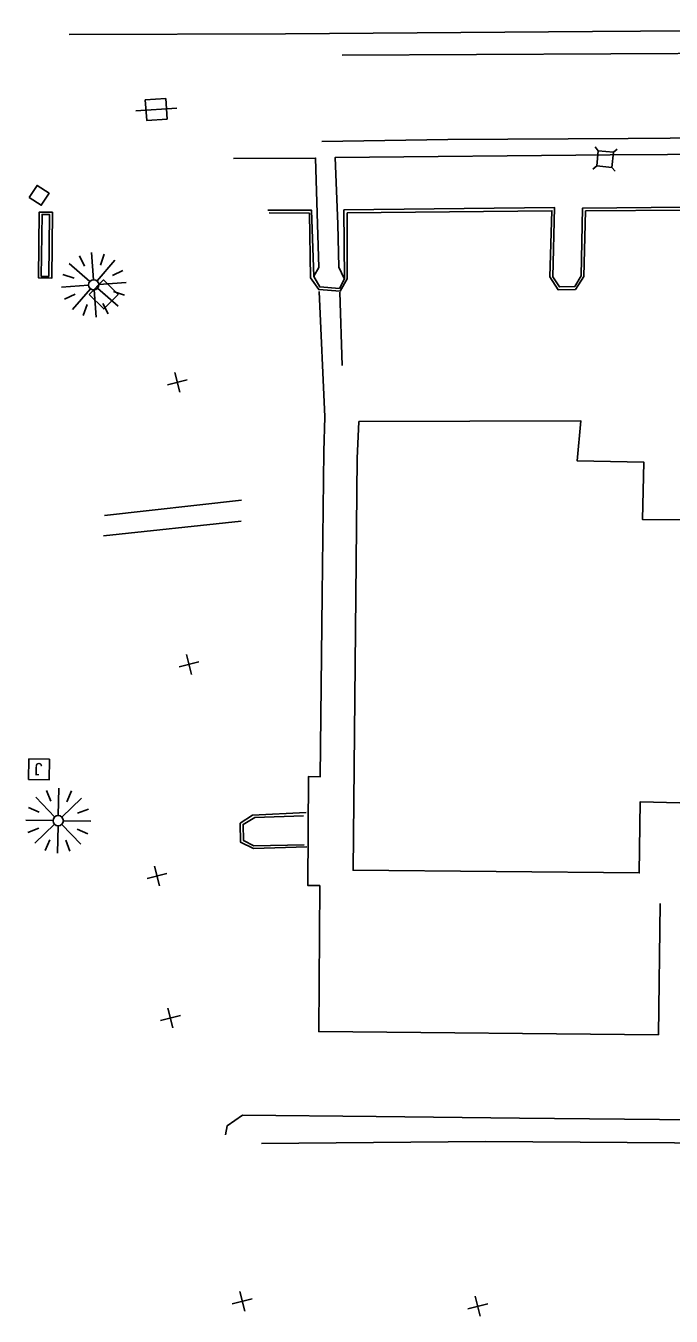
# Model space of a CAD drawing. Extents: x 4711259 to 4716401, y 890074 to 892728.
# Drawn here: x 4711259.2 to 4711416.6, y 891002.7 to 891317.2 of the extents above; entities that cross this region are included whole.
import ezdxf

# ---------------------------------------------------------------- set-up
doc = ezdxf.new("R2010")
doc.units = 0
for name, color, linetype in [('E_HY_STORM_Inlet', 7, 'Continuous'), ('E_RDWY_PHOTOG_Eave', 7, 'Continuous'), ('E_RDWY_ROAD_Curb', 7, 'Continuous'), ('E_RDWY_ROAD_EdgeConc', 7, 'Continuous'), ('E_RDWY_ROAD_Sidewalk', 7, 'Continuous'), ('E_RDWY_ROAD_Striping', 7, 'Continuous'), ('E_RDWY_ROAD_TBofCurb', 7, 'Continuous'), ('E_TERR_DTM_BrkLines', 7, 'Continuous'), ('E_TERR_DTM_RandomPt', 7, 'Continuous'), ('E_TRAF_ILLUM_Poles', 7, 'Continuous'), ('E_TRAF_PHOTOG_Signs', 7, 'Continuous'), ('E_UTIL_COMM_General', 7, 'Continuous'), ('E_UTIL_ELEC_GENERAL', 7, 'Continuous'), ('E_UTIL_ELEC_POLE', 7, 'Continuous'), ('E_UTIL_WTR_General', 7, 'Continuous')]:
    doc.layers.add(name, color=color, linetype=linetype)

msp = doc.modelspace()

# ---------------------------------------------------------------- linework, layer by layer
at = {"layer": 'E_HY_STORM_Inlet'}
msp.add_line((4711278.2, 891251.75), (4711278.2, 891251.75), dxfattribs=at)
msp.add_lwpolyline([(4711274.66, 891251.72), (4711278.17, 891255.28), (4711281.73, 891251.77), (4711278.22, 891248.21)], close=True, dxfattribs=at)
at = {"layer": 'E_RDWY_PHOTOG_Eave'}
msp.add_lwpolyline([(4711532.58, 891196.13), (4711493.22, 891196.36), (4711493.39, 891196.48), (4711409.65, 891196.87), (4711409.96, 891210.86), (4711393.66, 891211.19), (4711394.58, 891220.96), (4711340.47, 891220.75), (4711340.05, 891211.74), (4711339.04, 891111.37), (4711408.85, 891110.73), (4711409.1, 891128.06), (4711492.84, 891125.95), (4711531.9, 891125.61), (4711532.65, 891196.06)], dxfattribs=at)
at = {"layer": 'E_RDWY_ROAD_Curb'}
for points in [[(4711336.39, 891310.08), (4711434.66, 891310.58), (4711510.87, 891310.89), (4711572.62, 891311.17), (4711615.1, 891311.7)], [(4711318.59, 891271.61), (4711328.4, 891271.56), (4711328.68, 891255.8), (4711330.67, 891252.93), (4711335.93, 891252.55), (4711337.64, 891255.54), (4711337.63, 891271.62), (4711387.56, 891272.15), (4711387, 891256.05), (4711389.04, 891252.91), (4711393.27, 891252.99), (4711395.34, 891256.11), (4711395.75, 891272.12), (4711444.67, 891272.45)], [(4711327.63, 891125.43), (4711314.5, 891124.81), (4711311.5, 891122.83), (4711311.6, 891118.21), (4711314.74, 891116.66), (4711327.76, 891117.05)]]:
    msp.add_lwpolyline(points, dxfattribs=at)
at = {"layer": 'E_RDWY_ROAD_EdgeConc'}
msp.add_lwpolyline([(4711265.75, 891271.8), (4711265.58, 891255.74), (4711262.34, 891255.77), (4711262.51, 891271.83)], close=True, dxfattribs=at)
for points in [[(4711413.91, 891103.29), (4711413.52, 891071.28), (4711330.67, 891072.04), (4711330.92, 891107.64), (4711327.97, 891107.7), (4711328.2, 891134.27), (4711331.05, 891134.18), (4711331.53, 891178.5), (4711331.91, 891213.47), (4711332.13, 891221.94), (4711330.76, 891252.45)], [(4711335.81, 891252.3), (4711336.38, 891234.39)], [(4711311.8, 891201.62), (4711278.43, 891197.88)], [(4711278.15, 891192.9), (4711311.77, 891196.5)]]:
    msp.add_lwpolyline(points, dxfattribs=at)
at = {"layer": 'E_RDWY_ROAD_Sidewalk'}
for points in [[(4711620.01, 891291.07), (4711550.39, 891290.38), (4711491.78, 891290.18), (4711436.87, 891289.98), (4711406.11, 891289.74), (4711362.14, 891289.55)], [(4711331.46, 891289.05), (4711362.14, 891289.55)], [(4711329.48, 891256.17), (4711330.65, 891258.3), (4711330.37, 891268.91), (4711329.88, 891285.01), (4711309.9, 891284.91)], [(4711336.87, 891255.64), (4711335.57, 891258.42), (4711335.29, 891268.88), (4711334.66, 891285.1), (4711401.76, 891285.78), (4711471.79, 891286.18), (4711521.53, 891286.27), (4711576.93, 891286.64), (4711616.2, 891287.07), (4711620.16, 891287.14)]]:
    msp.add_lwpolyline(points, dxfattribs=at)
at = {"layer": 'E_RDWY_ROAD_Striping'}
msp.add_lwpolyline([(4711269.83, 891315.08), (4711322.53, 891315.28), (4711397.46, 891315.84), (4711456.03, 891316.25), (4711477.12, 891316.43), (4711546.25, 891316.78), (4711614.88, 891317.24)], dxfattribs=at)
at = {"layer": 'E_RDWY_ROAD_TBofCurb'}
for points in [[(4711336.8, 891272.38), (4711336.92, 891255.53), (4711335.73, 891253.21), (4711330.93, 891253.58), (4711329.44, 891256.1), (4711328.91, 891272.27), (4711318.29, 891272.31)], [(4711445.3, 891273.26), (4711394.99, 891272.77), (4711394.69, 891256.27), (4711393.13, 891253.71), (4711389.37, 891253.59), (4711387.77, 891256.08), (4711388.19, 891272.94), (4711336.8, 891272.38)], [(4711327.11, 891117.57), (4711314.87, 891117.31), (4711312.34, 891118.6), (4711312.21, 891122.54), (4711315.07, 891124.27), (4711326.93, 891124.62)], [(4711483.13, 891070.27), (4711480.91, 891070.32), (4711478.17, 891069.61), (4711475.63, 891065.85), (4711475.19, 891049.99), (4711430.84, 891050.48), (4711379.63, 891050.94), (4711344.67, 891051.38), (4711312.04, 891051.7), (4711308.36, 891049.09), (4711307.92, 891046.89)]]:
    msp.add_lwpolyline(points, dxfattribs=at)
at = {"layer": 'E_TERR_DTM_BrkLines'}
msp.add_lwpolyline([(4711316.73, 891044.73), (4711371.36, 891045.25), (4711429.02, 891044.86), (4711485.37, 891044.42), (4711545.06, 891043.32), (4711590.92, 891041.62), (4711616.39, 891039.65)], dxfattribs=at)
at = {"layer": 'E_TERR_DTM_RandomPt'}
for p, q in [((4711298.59, 891230.94), (4711293.75, 891229.69)), ((4711295.55, 891232.74), (4711296.8, 891227.9)), ((4711301.45, 891162.18), (4711296.61, 891160.93)), ((4711298.4, 891163.97), (4711299.65, 891159.13)), ((4711290.58, 891112.4), (4711291.83, 891107.56)), ((4711293.62, 891110.61), (4711288.78, 891109.35)), ((4711293.87, 891077.78), (4711295.12, 891072.94)), ((4711296.92, 891075.99), (4711292.08, 891074.74)), ((4711311.42, 891008.71), (4711312.62, 891003.86)), ((4711314.45, 891006.89), (4711309.59, 891005.69)), ((4711371.88, 891005.69), (4711367.03, 891004.49)), ((4711368.86, 891007.52), (4711370.06, 891002.67))]:
    msp.add_line(p, q, dxfattribs=at)
at = {"layer": 'E_TRAF_ILLUM_Poles'}
for p, q in [((4711274.84, 891254.91), (4711269.8, 891259.28)), ((4711273.54, 891258.64), (4711272.28, 891261.19)), ((4711275.69, 891255.34), (4711275.22, 891261.99)), ((4711276.6, 891255.04), (4711280.97, 891260.07)), ((4711277.41, 891258.89), (4711278.33, 891261.59)), ((4711270.99, 891255.72), (4711268.29, 891256.64)), ((4711282.88, 891257.59), (4711280.33, 891256.34)), ((4711274.54, 891254), (4711267.89, 891253.53)), ((4711274.96, 891253.15), (4711270.6, 891248.11)), ((4711276.73, 891253.27), (4711281.76, 891248.91)), ((4711277.03, 891254.18), (4711283.68, 891254.66)), ((4711271.23, 891251.85), (4711268.68, 891250.59)), ((4711275.87, 891252.85), (4711276.35, 891246.2)), ((4711283.28, 891251.55), (4711280.58, 891252.46)), ((4711273.24, 891246.6), (4711274.15, 891249.3)), ((4711279.28, 891246.99), (4711278.02, 891249.54)), ((4711265.31, 891128.18), (4711264.28, 891130.84)), ((4711267.15, 891124.71), (4711267.28, 891131.37)), ((4711270.34, 891130.7), (4711269.19, 891128.09)), ((4711266.26, 891124.36), (4711261.64, 891129.16)), ((4711268.03, 891124.33), (4711272.83, 891128.95)), ((4711262.5, 891125.51), (4711259.89, 891126.66)), ((4711274.52, 891126.31), (4711271.86, 891125.28)), ((4711265.88, 891123.48), (4711259.22, 891123.6)), ((4711262.41, 891121.63), (4711259.75, 891120.61)), ((4711266.23, 891122.59), (4711261.43, 891117.96)), ((4711267.11, 891122.21), (4711266.99, 891115.54)), ((4711268, 891122.56), (4711272.62, 891117.76)), ((4711268.38, 891123.43), (4711275.05, 891123.31)), ((4711274.37, 891120.25), (4711271.77, 891121.4)), ((4711265.08, 891118.82), (4711263.92, 891116.22)), ((4711269.98, 891116.07), (4711268.96, 891118.73))]:
    msp.add_line(p, q, dxfattribs=at)
for centre in [(4711275.78, 891254.09), (4711267.13, 891123.46)]:
    msp.add_circle(centre, 1.25, dxfattribs=at)
at = {"layer": 'E_TRAF_PHOTOG_Signs'}
msp.add_lwpolyline([(4711264.81, 891256.12), (4711264.99, 891271.24), (4711263.17, 891271.26), (4711262.99, 891256.14)], close=True, dxfattribs=at)
at = {"layer": 'E_UTIL_COMM_General'}
msp.add_lwpolyline([(4711260.05, 891275.4), (4711261.98, 891278.32), (4711264.9, 891276.4), (4711262.98, 891273.48)], close=True, dxfattribs=at)
at = {"layer": 'E_UTIL_ELEC_GENERAL'}
msp.add_lwpolyline([(4711259.98, 891138.51), (4711264.98, 891138.42), (4711264.88, 891133.42), (4711259.88, 891133.52)], close=True, dxfattribs=at)
at = {"layer": 'E_UTIL_ELEC_POLE'}
msp.add_line((4711286.04, 891296.52), (4711296.02, 891297.17), dxfattribs=at)
msp.add_lwpolyline([(4711288.37, 891299.18), (4711293.36, 891299.5), (4711293.69, 891294.52), (4711288.7, 891294.19)], close=True, dxfattribs=at)
at = {"layer": 'E_UTIL_WTR_General'}
for p, q in [((4711398.85, 891286.8), (4711398.11, 891287.72)), ((4711402.58, 891286.42), (4711403.49, 891287.16)), ((4711398.46, 891283.08), (4711397.55, 891282.33)), ((4711402.19, 891282.69), (4711402.93, 891281.77))]:
    msp.add_line(p, q, dxfattribs=at)
msp.add_lwpolyline([(4711398.46, 891283.08), (4711398.85, 891286.8), (4711402.58, 891286.42), (4711402.19, 891282.69)], close=True, dxfattribs=at)

# ---------------------------------------------------------------- texts
at = {"layer": 'E_UTIL_ELEC_GENERAL'}
msp.add_text('J', height=3, rotation=178.9017, dxfattribs=at).set_placement((4711263.31, 891137.52))

doc.saveas('drawing.dxf')
